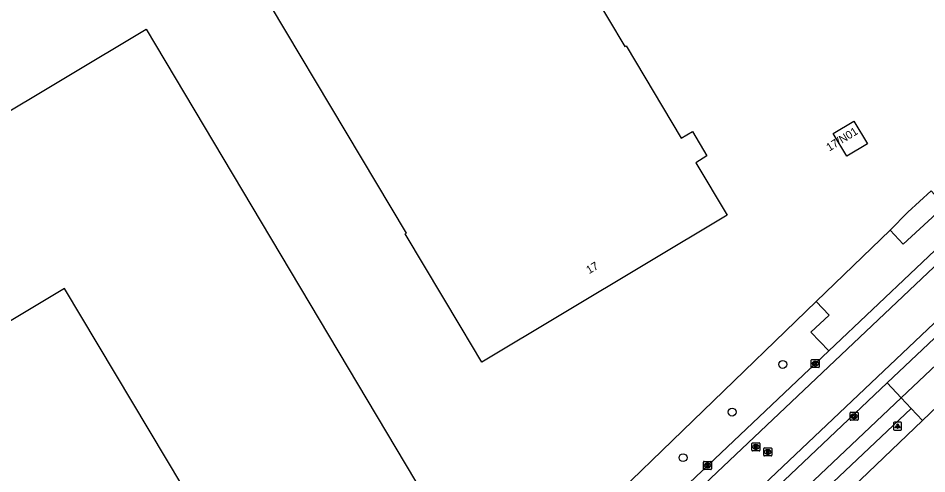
# Model space of a CAD drawing. Extents: x 156651 to 158072, y 387631 to 388990.
# Drawn here: x 157592.7 to 157706.2, y 388356.6 to 388413.4 of the extents above; entities that cross this region are included whole.
import ezdxf

# ---------------------------------------------------------------- set-up
doc = ezdxf.new("R2010")
doc.units = 0
for name, color, linetype in [('IMGEO_Berm_groen', 7, 'Continuous'), ('IMGEO_Boom', 7, 'Continuous'), ('IMGEO_Groenvoorziening', 7, 'Continuous'), ('IMGEO_Hek', 7, 'Continuous'), ('IMGEO_Kolk', 7, 'Continuous'), ('IMGEO_Lichtpunt', 7, 'Continuous'), ('IMGEO_Pand', 7, 'Continuous'), ('IMGEO_Pand_nummerreeks', 7, 'Continuous'), ('IMGEO_Rijbaan_lokaal_gesloten', 7, 'Continuous'), ('IMGEO_Rijbaan_lokaal_open', 7, 'Continuous'), ('IMGEO_Rioolput', 7, 'Continuous'), ('IMGEO_Voetpad_open', 7, 'Continuous')]:
    doc.layers.add(name, color=color, linetype=linetype)

msp = doc.modelspace()

# ---------------------------------------------------------------- linework, layer by layer
at = {"layer": 'IMGEO_Berm_groen'}
msp.add_lwpolyline([(157664.14, 388350.8), (157692.35, 388378.1)], dxfattribs=at)
at = {"layer": 'IMGEO_Boom'}
for centre in [(157688.2, 388370.24), (157681.87, 388364.29), (157675.75, 388358.6)]:
    msp.add_circle(centre, 0.489, dxfattribs=at)
at = {"layer": 'IMGEO_Groenvoorziening'}
for points in [[(157701.62, 388386.98), (157703.83, 388389.24), (157706.74, 388391.92)], [(157705.63, 388363.26), (157681.51, 388340.17), (157681.33, 388340)]]:
    msp.add_lwpolyline(points, dxfattribs=at)
at = {"layer": 'IMGEO_Hek'}
for points in [[(157701.62, 388386.98), (157703.83, 388389.24)], [(157692.35, 388378.1), (157664.14, 388350.8)]]:
    msp.add_lwpolyline(points, dxfattribs=at)
at = {"layer": 'IMGEO_Kolk'}
for p, q in [((157691.76, 388369.92), (157691.76, 388370.77)), ((157691.83, 388370.85), (157692.69, 388370.85)), ((157692.69, 388369.84), (157691.83, 388369.84)), ((157692.27, 388370.07), (157692.24, 388370.07)), ((157692.25, 388370.62), (157692.27, 388370.62)), ((157692.76, 388370.77), (157692.76, 388369.92)), ((157696.6, 388363.35), (157696.6, 388364.2)), ((157696.68, 388364.27), (157697.53, 388364.27)), ((157697.6, 388364.2), (157697.6, 388363.35)), ((157697.53, 388363.27), (157696.68, 388363.27)), ((157697.09, 388364.05), (157697.11, 388364.05)), ((157697.11, 388363.49), (157697.09, 388363.49)), ((157678.3, 388357.2), (157678.3, 388358.05)), ((157678.37, 388358.13), (157679.22, 388358.13)), ((157678.78, 388357.91), (157678.81, 388357.91)), ((157678.81, 388357.35), (157678.78, 388357.35)), ((157679.3, 388358.05), (157679.3, 388357.2)), ((157679.22, 388357.13), (157678.37, 388357.13))]:
    msp.add_line(p, q, dxfattribs=at)
for points in [[(157691.76, 388369.92), (157691.76, 388370.77)], [(157691.83, 388370.85), (157692.69, 388370.85)], [(157692.69, 388369.84), (157691.83, 388369.84)], [(157692.08, 388370.54), (157692.2, 388370.54), (157692.2, 388370.39), (157692.33, 388370.54), (157692.5, 388370.54), (157692.35, 388370.39), (157692.5, 388370.14), (157692.35, 388370.14), (157692.27, 388370.31), (157692.2, 388370.24), (157692.2, 388370.14), (157692.08, 388370.14), (157692.08, 388370.54)], [(157692.76, 388370.77), (157692.76, 388369.92)], [(157696.6, 388363.35), (157696.6, 388364.2)], [(157696.68, 388364.27), (157697.53, 388364.27)], [(157697.6, 388364.2), (157697.6, 388363.35)], [(157697.53, 388363.27), (157696.68, 388363.27)], [(157696.92, 388363.97), (157697.05, 388363.97), (157697.05, 388363.82), (157697.17, 388363.97), (157697.34, 388363.97), (157697.19, 388363.82), (157697.35, 388363.57), (157697.19, 388363.57), (157697.11, 388363.74), (157697.05, 388363.67), (157697.05, 388363.57), (157696.92, 388363.57), (157696.92, 388363.97)], [(157678.3, 388357.2), (157678.3, 388358.05)], [(157678.37, 388358.13), (157679.22, 388358.13)], [(157678.62, 388357.83), (157678.74, 388357.83), (157678.74, 388357.68), (157678.87, 388357.83), (157679.03, 388357.83), (157678.89, 388357.68), (157679.04, 388357.43), (157678.89, 388357.43), (157678.8, 388357.59), (157678.74, 388357.53), (157678.74, 388357.43), (157678.62, 388357.43), (157678.62, 388357.83)], [(157679.3, 388358.05), (157679.3, 388357.2)], [(157679.22, 388357.13), (157678.37, 388357.13)]]:
    msp.add_lwpolyline(points, dxfattribs=at)
for centre, start, end in [((157691.83, 388370.77), 91.552, 178.448), ((157691.83, 388370.77), 91.552, 178.448), ((157691.83, 388369.92), 181.552, 268.448), ((157691.83, 388369.92), 181.552, 268.448), ((157692.68, 388370.77), 1.552, 88.448), ((157692.68, 388370.77), 1.552, 88.448), ((157692.68, 388369.92), 271.552, 358.448), ((157692.68, 388369.92), 271.552, 358.448), ((157696.68, 388364.2), 91.552, 178.448), ((157696.68, 388364.2), 91.552, 178.448), ((157697.53, 388364.2), 1.552, 88.448), ((157697.53, 388364.2), 1.552, 88.448), ((157696.68, 388363.35), 181.552, 268.448), ((157696.68, 388363.35), 181.552, 268.448), ((157697.53, 388363.35), 271.552, 358.448), ((157697.53, 388363.35), 271.552, 358.448), ((157678.37, 388358.05), 91.552, 178.448), ((157678.37, 388358.05), 91.552, 178.448), ((157679.22, 388358.05), 1.552, 88.448), ((157679.22, 388358.05), 1.552, 88.448), ((157678.37, 388357.2), 181.552, 268.448), ((157678.37, 388357.2), 181.552, 268.448), ((157679.22, 388357.2), 271.552, 358.448), ((157679.22, 388357.2), 271.552, 358.448)]:
    msp.add_arc(centre, 0.0765, start, end, dxfattribs=at)
for centre, major_axis, ratio, start_param, end_param in [((157692.25, 388370.34), (-0.387, 0.002), 0.722429, 4.712389, 7.853982), ((157692.27, 388370.34), (-0.39, 0.002), 0.717154, 1.570796, 4.712389), ((157697.09, 388363.77), (-0.387, 0.002), 0.722429, 4.712389, 7.853982), ((157697.11, 388363.77), (-0.39, 0.002), 0.717154, 1.570796, 4.712389), ((157678.78, 388357.63), (-0.387, 0.002), 0.722429, 4.712389, 7.853982), ((157678.81, 388357.63), (-0.39, 0.002), 0.717154, 1.570796, 4.712389)]:
    msp.add_ellipse(centre, major_axis=major_axis, ratio=ratio, start_param=start_param, end_param=end_param, dxfattribs=at)
at = {"layer": 'IMGEO_Lichtpunt'}
for p, q in [((157702.04, 388362.94), (157702.04, 388362.13)), ((157702.04, 388362.94), (157702.04, 388362.13)), ((157702.94, 388363.03), (157702.13, 388363.03)), ((157702.94, 388363.03), (157702.13, 388363.03)), ((157703.03, 388362.13), (157703.03, 388362.94)), ((157703.03, 388362.13), (157703.03, 388362.94)), ((157702.13, 388362.03), (157702.94, 388362.03)), ((157702.13, 388362.03), (157702.94, 388362.03))]:
    msp.add_line(p, q, dxfattribs=at)
for points in [[(157702.41, 388362.6), (157702.45, 388362.57), (157702.26, 388362.31), (157702.22, 388362.34), (157702.41, 388362.6)], [(157702.51, 388362.55), (157702.56, 388362.55), (157702.56, 388362.23), (157702.51, 388362.23), (157702.51, 388362.55)], [(157702.62, 388362.57), (157702.66, 388362.6), (157702.85, 388362.34), (157702.81, 388362.31), (157702.62, 388362.57)]]:
    msp.add_lwpolyline(points, dxfattribs=at)
msp.add_circle((157702.54, 388362.73), 0.0994, dxfattribs=at)
for centre, start, end in [((157702.13, 388362.94), 90, 180), ((157702.13, 388362.94), 90, 180), ((157702.94, 388362.94), 0, 90), ((157702.94, 388362.94), 0, 90), ((157702.13, 388362.13), 180, 270), ((157702.13, 388362.13), 180, 270), ((157702.94, 388362.13), 270, 0), ((157702.94, 388362.13), 270, 360)]:
    msp.add_arc(centre, 0.0946, start, end, dxfattribs=at)
at = {"layer": 'IMGEO_Pand'}
for points in [[(157631.64, 388472.01), (157631.96, 388471.47), (157631.78, 388471.36), (157668.46, 388409.9), (157668.64, 388410.01), (157675.52, 388398.48), (157676.92, 388399.29), (157678.73, 388396.27), (157677.36, 388395.41), (157681.27, 388388.86), (157650.6, 388370.54), (157648.03, 388374.83), (157641.03, 388386.53), (157641.19, 388386.63), (157616.7, 388427.68), (157614.69, 388426.48), (157614.79, 388426.31), (157614.49, 388426.13), (157598.75, 388452.49), (157599.06, 388452.67), (157631.64, 388472.01)], [(157568.36, 388387.95), (157608.72, 388412.07), (157643.51, 388353.72), (157638.47, 388350.75), (157637.34, 388350.08), (157639.86, 388345.86), (157642.29, 388341.78), (157641.93, 388341.56), (157641.69, 388341.95), (157640.76, 388343.52), (157615.8, 388328.62), (157609.9, 388338.49), (157619.66, 388344.34), (157598.51, 388379.7), (157579.92, 388368.61), (157519.84, 388332.72), (157508.27, 388352.09), (157568.36, 388387.95)], [(157697.08, 388400.6), (157698.78, 388397.76), (157696.21, 388396.22), (157694.5, 388399.04), (157697.08, 388400.6)]]:
    msp.add_lwpolyline(points, dxfattribs=at)
at = {"layer": 'IMGEO_Rijbaan_lokaal_gesloten'}
for points in [[(157798.5, 388468.9), (157722.58, 388397.08), (157652.85, 388331.14), (157631.52, 388311.46), (157630.13, 388310.36), (157626, 388307.51), (157618.61, 388303.12), (157611.95, 388299.92), (157602.83, 388296.9), (157595.29, 388295.3), (157579.39, 388291.92), (157574.82, 388290.77), (157572.31, 388289.99), (157568.36, 388288.55), (157564.86, 388287.11), (157558.87, 388284.45), (157552.81, 388281.47), (157550.71, 388280.34), (157545.33, 388277.25), (157544.74, 388276.91)], [(157721.21, 388397.73), (157693.94, 388371.93)], [(157728.66, 388395.81), (157727.54, 388394.74), (157640.15, 388312.04), (157636.58, 388308.8), (157634.21, 388306.87), (157632.08, 388305.29), (157628, 388302.53), (157625.29, 388300.87), (157620.98, 388298.49), (157615.78, 388295.99), (157610.41, 388293.8), (157606.72, 388292.52), (157604.18, 388291.91), (157580.33, 388286.85)], [(157701.24, 388367.93), (157708.58, 388374.87)], [(157693.94, 388371.93), (157669.38, 388348.69)], [(157678.71, 388346.61), (157701.24, 388367.93)]]:
    msp.add_lwpolyline(points, dxfattribs=at)
at = {"layer": 'IMGEO_Rijbaan_lokaal_open'}
for points in [[(157701.62, 388386.98), (157703.23, 388385.26), (157708.43, 388390.04), (157706.74, 388391.92)], [(157692.35, 388378.1), (157701.62, 388386.98)], [(157692.35, 388378.1), (157693.97, 388376.4), (157691.71, 388374.28), (157693.94, 388371.93)]]:
    msp.add_lwpolyline(points, dxfattribs=at)
at = {"layer": 'IMGEO_Rioolput'}
for p, q in [((157684.34, 388359.52), (157684.34, 388360.37)), ((157684.41, 388360.45), (157685.26, 388360.45)), ((157684.82, 388360.23), (157684.85, 388360.23)), ((157684.85, 388359.67), (157684.82, 388359.67)), ((157685.34, 388360.37), (157685.34, 388359.52)), ((157685.82, 388358.9), (157685.82, 388359.75)), ((157685.9, 388359.83), (157686.75, 388359.83)), ((157686.31, 388359.6), (157686.34, 388359.6)), ((157686.83, 388359.75), (157686.83, 388358.9)), ((157685.26, 388359.45), (157684.41, 388359.45)), ((157686.75, 388358.82), (157685.9, 388358.82)), ((157686.33, 388359.05), (157686.31, 388359.05))]:
    msp.add_line(p, q, dxfattribs=at)
for points in [[(157684.34, 388359.52), (157684.34, 388360.37)], [(157684.41, 388360.45), (157685.26, 388360.45)], [(157684.93, 388360.15), (157684.67, 388360.15), (157684.67, 388359.75)], [(157684.67, 388359.75), (157684.8, 388359.75), (157684.8, 388359.91), (157684.81, 388359.91)], [(157684.85, 388360.07), (157684.8, 388360.07), (157684.8, 388359.99)], [(157684.8, 388359.99), (157684.85, 388359.99)], [(157684.85, 388359.88), (157684.93, 388359.75), (157685.07, 388359.75), (157685, 388359.87)], [(157685.34, 388360.37), (157685.34, 388359.52)], [(157685.82, 388358.9), (157685.82, 388359.75)], [(157685.9, 388359.83), (157686.75, 388359.83)], [(157686.41, 388359.52), (157686.16, 388359.52), (157686.16, 388359.12)], [(157686.83, 388359.75), (157686.83, 388358.9)], [(157685.26, 388359.45), (157684.41, 388359.45)], [(157686.75, 388358.82), (157685.9, 388358.82)], [(157686.16, 388359.12), (157686.29, 388359.12), (157686.29, 388359.29), (157686.3, 388359.29)], [(157686.34, 388359.44), (157686.29, 388359.44), (157686.29, 388359.36)], [(157686.29, 388359.36), (157686.34, 388359.36)], [(157686.34, 388359.26), (157686.41, 388359.12), (157686.55, 388359.12), (157686.49, 388359.25)]]:
    msp.add_lwpolyline(points, dxfattribs=at)
for centre, radius, start, end in [((157684.41, 388360.37), 0.0765, 91.552, 178.448), ((157684.41, 388360.37), 0.0765, 91.552, 178.448), ((157684.41, 388359.52), 0.0765, 181.552, 268.448), ((157684.41, 388359.52), 0.0765, 181.552, 268.448), ((157684.81, 388359.86), 0.0533, 26.0293, 88.6989), ((157684.86, 388359.97), 0.0964, 77.0061, 93.1865), ((157684.83, 388360.18), 0.19, 274.7715, 282.9687), ((157684.87, 388360.03), 0.0378, 276.6634, 79.6772), ((157684.92, 388360.04), 0.109, 350.3612, 89.416), ((157684.92, 388360.04), 0.112, 277.5842, 350.9817), ((157684.91, 388359.82), 0.108, 29.5134, 73.7905), ((157685.26, 388360.37), 0.0765, 1.552, 88.448), ((157685.26, 388360.37), 0.0765, 1.552, 88.448), ((157685.26, 388359.52), 0.0765, 271.552, 358.448), ((157685.26, 388359.52), 0.0765, 271.552, 358.448), ((157685.9, 388359.75), 0.0765, 91.552, 178.448), ((157685.9, 388359.75), 0.0765, 91.552, 178.448), ((157686.41, 388359.41), 0.109, 350.3612, 89.416), ((157686.75, 388359.75), 0.0765, 1.552, 88.448), ((157686.75, 388359.75), 0.0765, 1.552, 88.448), ((157685.9, 388358.9), 0.0765, 181.552, 268.448), ((157685.9, 388358.9), 0.0765, 181.552, 268.448), ((157686.29, 388359.23), 0.0533, 26.0293, 88.6989), ((157686.34, 388359.35), 0.0964, 77.0061, 93.1865), ((157686.32, 388359.55), 0.19, 274.7715, 282.9687), ((157686.36, 388359.4), 0.0378, 276.6634, 79.6772), ((157686.41, 388359.41), 0.112, 277.5842, 350.9817), ((157686.39, 388359.2), 0.108, 29.5134, 73.7905), ((157686.75, 388358.9), 0.0765, 271.552, 358.448), ((157686.75, 388358.9), 0.0765, 271.552, 358.448)]:
    msp.add_arc(centre, radius, start, end, dxfattribs=at)
for centre, major_axis, ratio, start_param, end_param in [((157684.82, 388359.95), (-0.387, 0.002), 0.722429, 4.712389, 7.853982), ((157684.85, 388359.95), (-0.39, 0.002), 0.717154, 1.570796, 4.712389), ((157686.31, 388359.32), (-0.387, 0.002), 0.722429, 4.712389, 7.853982), ((157686.34, 388359.32), (-0.39, 0.002), 0.717154, 1.570796, 4.712389)]:
    msp.add_ellipse(centre, major_axis=major_axis, ratio=ratio, start_param=start_param, end_param=end_param, dxfattribs=at)
at = {"layer": 'IMGEO_Voetpad_open'}
for points in [[(157703, 388366.07), (157710.33, 388373.02)], [(157712.55, 388369.82), (157711.36, 388368.68), (157705.63, 388363.26)], [(157701.24, 388367.93), (157703, 388366.07)], [(157680.45, 388344.77), (157703, 388366.07)], [(157703, 388366.07), (157704.25, 388364.75)], [(157681.71, 388343.47), (157704.25, 388364.75)], [(157704.25, 388364.75), (157705.63, 388363.26)]]:
    msp.add_lwpolyline(points, dxfattribs=at)

# ---------------------------------------------------------------- texts
at = {"layer": 'IMGEO_Pand_nummerreeks'}
for s, rotation, p in [('17/N01', 31.6287, (157694.01, 388396.8)), ('17', 30.84, (157664.01, 388381.49))]:
    msp.add_text(s, height=1, rotation=rotation, dxfattribs=at).set_placement(p)

doc.saveas('drawing.dxf')
